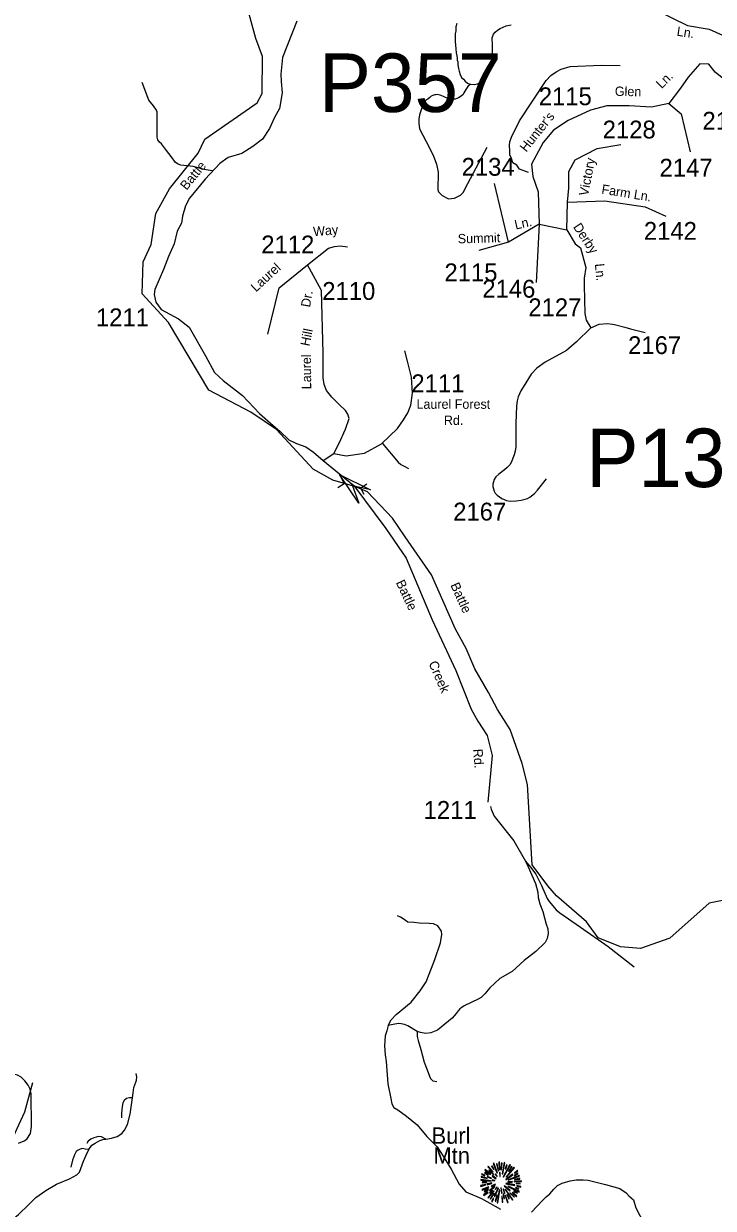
# Model space of a CAD drawing. Extents: x 884530 to 1028605, y 526725 to 653634.
# Drawn here: x 938802 to 943636, y 588671 to 596972 of the extents above; entities that cross this region are included whole.
import ezdxf

# ---------------------------------------------------------------- set-up
doc = ezdxf.new("R2010")
doc.units = 0
for name, color, linetype in [('Exist Geographical Mountain Summit CELL', 7, 'Continuous'), ('Exist Geographical Mountain Summit Label', 7, 'Continuous'), ('Exist Hydrographic Creek Single Shore', 7, 'Continuous'), ('Exist Hydrographic Creek Single Shore Label', 7, 'Continuous'), ('Exist Road Non-System Type 51', 7, 'Continuous'), ('Exist Road Secondary Structure Pipe Attributed CELL', 7, 'Continuous'), ('Exist Road Secondary Structure Pipe CELL', 7, 'Continuous'), ('Exist Road Secondary Structure Pipe Number Label', 7, 'Continuous'), ('Exist Road Secondary Type 51 Attributed', 7, 'Continuous'), ('Exist Road Secondary Type 51 Label', 7, 'Continuous'), ('Exist Road Secondary Type 51 Number Label', 7, 'Continuous')]:
    doc.layers.add(name, color=color, linetype=linetype)

msp = doc.modelspace()

# ---------------------------------------------------------------- linework, layer by layer
at = {"layer": 'Exist Geographical Mountain Summit CELL'}
for points in [[(942034.4, 588937.6), (942074.1, 588907), (942076.3, 588909.2), (942038.1, 588942)], [(942054.8, 588962.3), (942090.8, 588924.9), (942094.1, 588927.4), (942058.8, 588967)], [(942062.8, 588934.6), (942095.5, 588905.6), (942097.7, 588907.8), (942065.7, 588939.8)], [(942082.4, 588963.7), (942098, 588942), (942099.8, 588943.4), (942086.4, 588967.8)], [(942093.3, 588985.6), (942119.5, 588918.7), (942122.4, 588919.7), (942098.4, 588988.1)], [(942127.1, 588933.6), (942129.6, 588934.3), (942120.6, 588982.2), (942116.2, 588981.2)], [(942131.8, 588995), (942135.9, 588943), (942139.1, 588943.4), (942137.7, 588996.1)], [(942147.9, 588940.9), (942151.8, 588940.9), (942155.4, 588988.1), (942150, 588988.1)], [(942159.8, 588912.5), (942174.7, 588989.5), (942169.2, 588991.3), (942156.6, 588913.2)], [(942163.1, 588890.7), (942166, 588888.9), (942214.7, 588973.5), (942209.2, 588977.2)], [(942177.6, 588947.7), (942180.9, 588946.6), (942190.4, 588973.5), (942185.6, 588975.3)], [(942184.1, 588892.1), (942186.4, 588890), (942241.9, 588954.3), (942237.9, 588959)], [(942221.6, 588963.7), (942200.5, 588930.3), (942203.5, 588929.2), (942225.9, 588960.5)], [(942241.9, 588920.1), (942243.8, 588917.6), (942266.6, 588933.9), (942263, 588937.6)], [(942006, 588867.4), (942078.1, 588860.5), (942078.4, 588863.4), (942006, 588872.5)], [(942008.7, 588888.5), (942050.1, 588879), (942051.2, 588882.3), (942009.8, 588893.2)], [(942011.6, 588907.8), (942034, 588899.1), (942035.2, 588902), (942013, 588912.9)], [(942018.1, 588850), (942047.9, 588851.4), (942047.9, 588855.1), (942017, 588855.1)], [(942033.4, 588918.7), (942059.2, 588902.3), (942061.4, 588904.9), (942036.2, 588922.7)], [(942050.1, 588890.7), (942080.6, 588878.7), (942081.7, 588880.8), (942052.3, 588894.7)], [(942050.5, 588841), (942051.5, 588836.2), (942084.6, 588844.6), (942083.9, 588848.2)], [(942078.1, 588826.7), (942080.3, 588822), (942109, 588837.2), (942107.9, 588840.6)], [(942086.4, 588896.1), (942111.5, 588877.2), (942113.6, 588880.1), (942089, 588899.4)], [(942086.7, 588866.3), (942103.8, 588864.1), (942104.2, 588866.3), (942087.5, 588870.7)], [(942106.1, 588909.2), (942119.9, 588892.8), (942122, 588895), (942109.3, 588912.2)], [(942137.3, 588921.6), (942138.7, 588892.5), (942141.3, 588892.8), (942141.3, 588921.9)], [(942180.9, 588872.2), (942182.7, 588869.6), (942231.4, 588905.6), (942228.2, 588910)], [(942182.3, 588842.8), (942243.1, 588830.8), (942244.1, 588835.1), (942183.4, 588846.4)], [(942196.9, 588856.6), (942196.9, 588853.7), (942227, 588853.7), (942227.8, 588858.7)], [(942197.9, 588869.3), (942199, 588867), (942277.2, 588895.7), (942275.4, 588900.5)], [(942240.1, 588855.5), (942292.5, 588858.7), (942292.8, 588863.4), (942240.5, 588858.7)], [(942241.9, 588897.3), (942269.5, 588912.2), (942266.6, 588917.2), (942240.5, 588899.8)], [(942243.8, 588869.3), (942280.5, 588875.8), (942279, 588881.2), (942242.3, 588871.5)], [(942255, 588843.5), (942281.5, 588841.2), (942281.5, 588845.6), (942255.4, 588846.7)], [(942004.6, 588829.7), (942006, 588824.5), (942042.1, 588835.1), (942039.9, 588838.4)], [(942014.4, 588802), (942017, 588797.3), (942062.4, 588817.3), (942061, 588822)], [(942025.7, 588765.3), (942028.6, 588761.3), (942057, 588782.4), (942054.4, 588785.6)], [(942031.9, 588786), (942061, 588802.7), (942058.8, 588806.4), (942029.7, 588791.1)], [(942056.6, 588745.7), (942059.5, 588743.2), (942100.2, 588790.8), (942097.3, 588792.9)], [(942071.9, 588777), (942091.2, 588795.1), (942087.8, 588797.3), (942067.5, 588780.2)], [(942068.2, 588795.5), (942071.1, 588791.8), (942105.7, 588820.2), (942103.8, 588822.7)], [(942096.6, 588777), (942071.5, 588737.7), (942074.7, 588735.2), (942100.6, 588774.8)], [(942099.8, 588755.5), (942104.2, 588753.7), (942130.8, 588812.2), (942128.2, 588813)], [(942106.8, 588804.9), (942110, 588802), (942120.2, 588818.4), (942118.3, 588819.8)], [(942111.5, 588720.3), (942123.5, 588763.1), (942119.9, 588763.5), (942107.1, 588721.3)], [(942121.3, 588710.1), (942126, 588709), (942138.7, 588798.3), (942135.5, 588799.1)], [(942146.7, 588814), (942150.7, 588777), (942155.1, 588777.3), (942150, 588814.8)], [(942162.8, 588805.3), (942171.5, 588775.5), (942175.5, 588777.3), (942164.9, 588806.4)], [(942172.5, 588738.8), (942167.1, 588768.6), (942163.8, 588768.6), (942168.2, 588737.7)], [(942171.1, 588825.7), (942209.6, 588790.4), (942212.1, 588794.7), (942172.9, 588827.9)], [(942177.3, 588803.1), (942227.8, 588728.3), (942231.4, 588731.1), (942179.8, 588804.2)], [(942177.3, 588760.3), (942194.7, 588710.4), (942199, 588712.2), (942180.2, 588761)], [(942187.8, 588766), (942203.8, 588736.6), (942207.8, 588738.8), (942191.5, 588767.5)], [(942196.1, 588823.1), (942274.3, 588784.9), (942276.1, 588790.4), (942197.6, 588826)], [(942209.6, 588777.3), (942239.7, 588748.2), (942243.1, 588750.8), (942211.8, 588779.8)], [(942226.3, 588778), (942256.8, 588752.2), (942260.1, 588755.9), (942228.2, 588780.6)], [(942235.4, 588789), (942260.5, 588775.9), (942263, 588779.5), (942237.6, 588792.9)], [(942249.6, 588813), (942270.7, 588804.9), (942272.5, 588809.3), (942251, 588816.2)], [(942259.1, 588826.3), (942287.4, 588819.1), (942288.1, 588824.5), (942260.1, 588830.8)], [(942081.7, 588718.4), (942086.4, 588715.6), (942097.3, 588740.2), (942094.1, 588742.4)], [(942152.9, 588755.5), (942156.6, 588713), (942160.6, 588714), (942157.2, 588755.5)]]:
    msp.add_lwpolyline(points, close=True, dxfattribs=at)
at = {"layer": 'Exist Hydrographic Creek Single Shore'}
for points in [[(943782.9, 590844.9), (943606.5, 590809), (943332.5, 590564.2), (943125.1, 590492.5), (942986.9, 590502.4), (942829, 590566.6), (942748.5, 590679.3), (942536.2, 590859.6), (942477, 590931.2), (942365.9, 591076.9), (942333.9, 591640.6), (942296.8, 591788.8), (942212.9, 592025.9), (942124.1, 592166.7), (942060.6, 592286.2), (941964.4, 592452.2), (941902.9, 592594.6), (941828.6, 592728.3), (941660.8, 593109.5), (941475, 593376.6), (941386.8, 593507.7), (941211.6, 593692.4), (941122.7, 593728.8), (940969.3, 593772.8), (940830.4, 593851.1), (940573.5, 594128.6), (940394.4, 594250.3), (940099.6, 594403.9), (939816.5, 594878.9), (939631.9, 595079.5), (939639.8, 595302.5), (939694.4, 595426.1), (939727, 595642), (939825.1, 595814), (940025.8, 596065.9), (940071, 596163.5), (940438.8, 596418.6), (940474.4, 596483.5), (940475.5, 596742.7), (940429.8, 596868.3), (940324.6, 597254.9)], [(936105.3, 585081.1), (936369.8, 585037.6), (936778.8, 585049.1), (936839.7, 585123.3), (936938.6, 585551.3), (936941.3, 586092.7), (936919.1, 586168.6), (936927.8, 586411.3), (936868.3, 586612.7), (936773.8, 586768.8), (936767.5, 586824.7), (936727.6, 586878), (936712.8, 587160.5), (936783, 587257.6), (937200.6, 587511.7), (937468.6, 587775.4), (938034.1, 588430.2), (938569.9, 588954.3), (938700.6, 589109.3), (938809.1, 589346.7), (938866.6, 589552.2)]]:
    msp.add_lwpolyline(points, dxfattribs=at)
at = {"layer": 'Exist Road Non-System Type 51'}
for points in [[(941839, 596973.4), (941832.3, 596951.4), (941830.2, 596921.4), (941826.5, 596902.3), (941827.2, 596878.2), (941826.5, 596847.4), (941827.9, 596821.1), (941832.3, 596796.1), (941834.5, 596769.1), (941837.4, 596746.3), (941840.4, 596730.3), (941840.4, 596717.8), (941844.7, 596704.6), (941845.5, 596683.4), (941849.8, 596657.7), (941855, 596639.4), (941861.6, 596616.7), (941870.3, 596596.2), (941885.1, 596584.5), (941897.5, 596569.8), (941913.6, 596555.9), (941925.3, 596550.8), (941934.1, 596548.8)], [(941934.1, 596548.8), (941962.1, 596545.6), (941983.2, 596550.1), (942006.6, 596558.1), (942023.3, 596569.6), (942039.9, 596589.5), (942049.8, 596609.4), (942069.5, 596635.7), (942083.6, 596662.1), (942090.6, 596722), (942088.8, 596774.8), (942088.8, 596822.3), (942087.1, 596873.4), (942095.3, 596899.2), (942107, 596912.9), (942123.1, 596926.1), (942141, 596937.9), (942162.3, 596949), (942184.3, 596957.2), (942218.2, 596963.9)], [(942340.3, 595928.4), (942278.1, 595953.7), (942258.9, 595980.5), (942232, 595997.8), (942220.5, 596028.4), (942210.9, 596053.4), (942209, 596082.2), (942207, 596118.6), (942210.9, 596145.5), (942220.5, 596176.1), (942278.1, 596292.2), (942464.9, 596573.9), (942497.5, 596608.7), (942535, 596635.6), (942570.8, 596654.2), (942633.1, 596672.9), (942851.1, 596680.8), (942983, 596679.6)], [(940122.1, 595940.5), (940067.3, 595950.3), (939991, 595972), (939903.6, 595981.5), (939884.1, 595987.6), (939867.1, 595998.5), (939835.5, 596041), (939803.9, 596084.8), (939768.7, 596131), (939752.9, 596141.9), (939741.9, 596157.7), (939737.1, 596178.3), (939737.3, 596352.8), (939733.5, 596365.3), (939710.8, 596396.7), (939679.5, 596436.9), (939633, 596560)], [(941934.1, 596548.8), (941914.8, 596531.6), (941909.9, 596524.3), (941902.1, 596512.3), (941894.9, 596498.9), (941888.3, 596487.9), (941882.3, 596475.4), (941867.6, 596463.3), (941849.9, 596452.9), (941837.8, 596447.2), (941826.2, 596443.6), (941814.5, 596442.3), (941802.9, 596443.4), (941791.1, 596445.8), (941781.8, 596447.7), (941771.1, 596450.5), (941757.9, 596455.4), (941744, 596461.7), (941732.1, 596467.9), (941721.5, 596471.8), (941710.8, 596473.2), (941699.6, 596475.7), (941690.8, 596474.7), (941680.7, 596473.2), (941657.3, 596463.5), (941648, 596456.2), (941633.9, 596444.5), (941622.1, 596435.3), (941611, 596419.2), (941594.9, 596389.7), (941577.4, 596334.2), (941572.7, 596302.4), (941571.1, 596275.4), (941577.4, 596235.8), (941623.5, 596146.9), (941672.6, 596050.1), (941696.5, 595988.2), (941707.5, 595932.7), (941706, 595810.6), (941710.7, 595793.1), (941736.1, 595767.7), (941778.9, 595745.5), (941821.9, 595750.3), (941863.1, 595770.9), (941883.7, 595790), (941915.5, 595853.4), (942050.3, 596107.3)], [(941316.7, 594031.3), (941426.3, 593898.4), (941445.4, 593883.7), (941470.3, 593870.5), (941499.7, 593855.8)], [(942074.4, 591485.7), (942079, 591467.8), (942101, 591419.1), (942238.6, 591245.8), (942320.7, 591103.5)], [(942320.7, 591103.5), (942337.4, 591062.9), (942389.6, 590946.3), (942405.9, 590885.5), (942407.5, 590849.7), (942419.4, 590804.9), (942440.3, 590750.8), (942464, 590661.1), (942475.7, 590629.6), (942479.1, 590595.7), (942470.9, 590560.6), (942456.6, 590533.4), (942393, 590471.2), (942310.8, 590407.4), (942225.6, 590331.3), (942140.6, 590281.3), (942070.8, 590214.6), (942033.9, 590173), (942007.9, 590149.1), (941987.5, 590135.5), (941943.3, 590114.4), (941890.2, 590088.9), (941873.3, 590077.8), (941860.1, 590068.9), (941848.1, 590054.1), (941832.9, 590034.9), (941805.3, 590002.2), (941702.2, 589918.7), (941656.8, 589900.5), (941620.3, 589896), (941583.9, 589902.1), (941559.6, 589909.7)], [(942320.7, 591103.5), (942353.7, 591061.2), (942391.1, 591012.7), (942433.1, 590931.7), (942472.1, 590842.1), (942484.6, 590820.7), (942534.4, 590762.1), (942560.8, 590740.4), (942704.4, 590640.8), (942899.8, 590506.5), (943081.9, 590363.3)], [(941357, 589951.5), (941377.9, 589991.7), (941413.7, 590029), (941517.4, 590115), (941581.7, 590194.1), (941624.3, 590256.6), (941659.9, 590352.8), (941685.3, 590414), (941724, 590531.9), (941733, 590588.5), (941730, 590612.4), (941706.1, 590649.8), (941674.8, 590664.7), (941644.9, 590666.1), (941577.6, 590667.8), (941537.2, 590672.8), (941495.7, 590676.6), (941461.5, 590699), (941443.8, 590710.8), (941421.3, 590720.1)], [(941357, 589951.5), (941346.5, 589914.1), (941336.1, 589878.3), (941331.7, 589809.7), (941336.1, 589747), (941342.6, 589700.4), (941354.5, 589542.4), (941375.7, 589440), (941382.3, 589403.8), (941395.9, 589377), (941425.6, 589360.5), (941485.4, 589315.8), (941561.4, 589256.1), (941627.7, 589173.5), (941699.8, 589101.1), (941743.5, 589037.2), (941798.2, 588943.9), (941835.9, 588875.6), (941855.2, 588839.8), (941901.6, 588786.1), (942010.6, 588738.4), (942144.9, 588665.1)], [(941559.6, 589909.7), (941495.9, 589949.1), (941471.7, 589958.2), (941448.4, 589963.2), (941432.8, 589965), (941403.2, 589961.9), (941379.9, 589957.4), (941357, 589951.5)], [(941559.6, 589909.7), (941559.6, 589874.8), (941566.9, 589845.7), (941587, 589784.4), (941608.6, 589694.9), (941631.1, 589640.4), (941646.7, 589597.5), (941654.7, 589581.1), (941671.1, 589563.8), (941698.8, 589559.8)], [(938764.5, 589127), (938805.4, 589142.9), (938823.9, 589156.1), (938850.3, 589194.3), (938856.9, 589243.2), (938856.9, 589313.1), (938854.7, 589403), (938854.7, 589472.6), (938847.4, 589506.4), (938832.6, 589533.8), (938810.5, 589564.4), (938784.1, 589589.7), (938758.8, 589603.4), (938730.3, 589609.7), (938700.8, 589607.6), (938664.9, 589603.4), (938628, 589597.1), (938601.6, 589592.8)], [(939564.3, 589443.8), (939568.3, 589479.4), (939574.9, 589517.7), (939588.2, 589554.7), (939592.1, 589569.2), (939594.8, 589591.6), (939590.8, 589615.4)], [(939377, 589156.1), (939416.6, 589162.6), (939457.5, 589173.2), (939489.2, 589195.6), (939507.6, 589218.1), (939530.1, 589259), (939548.5, 589330.2), (939564.3, 589443.8)], [(939564.3, 589443.8), (939544.6, 589445.1), (939522.2, 589441.1), (939506.3, 589426.6), (939497.1, 589409.5), (939491.8, 589384.4), (939490.5, 589360.6), (939487.8, 589335.6), (939486.5, 589305.2)], [(939377, 589156.1), (939346.5, 589172), (939325.5, 589174.5), (939292.5, 589165.3), (939271.4, 589154.8), (939254.2, 589141.5), (939244.3, 589124.3)], [(939258.2, 589082.1), (939280.6, 589112.5), (939301.8, 589128.3), (939334.8, 589145.5), (939357.2, 589152.1), (939377, 589156.1)], [(938592.9, 588494.8), (938645.7, 588531.8), (938676, 588555.5), (938765.9, 588628), (938837.1, 588698.1), (938887.3, 588745.5), (938955.9, 588795.7), (939032.5, 588839.3), (939122.2, 588877.5), (939175, 588905.2), (939192.2, 588923.7), (939221.3, 589001.6), (939239.7, 589042.6), (939258.2, 589082.1)], [(939258.2, 589082.1), (939231.7, 589084.7), (939212, 589088.7), (939197.4, 589084.7), (939184.3, 589078.2), (939168.5, 589069), (939157.9, 589046.5), (939143.4, 589008.2), (939131.5, 588959.4)], [(942362.7, 588642.9), (942400, 588683.2), (942441.7, 588728), (942465.6, 588751.8), (942489.5, 588771.2), (942519.3, 588805.5), (942544.7, 588830.9), (942577.5, 588847.3), (942632.7, 588863.8), (942676, 588871.2), (942723.8, 588869.7), (942759.6, 588868.2), (942880.4, 588836.9), (942923.7, 588826.4), (942980.4, 588808.5), (943025.9, 588778.5), (943045, 588758.6), (943077.4, 588729.4), (943092.4, 588674.2), (943180.3, 588507.1)]]:
    msp.add_lwpolyline(points, dxfattribs=at)
at = {"layer": 'Exist Road Secondary Structure Pipe Attributed CELL'}
msp.add_lwpolyline([(941150.9, 593611.6), (941014.7, 593813.8), (941233.8, 593706.8), (941106.7, 593733.7)], close=True, dxfattribs=at)
at = {"layer": 'Exist Road Secondary Structure Pipe CELL'}
for p, q in [((941005, 593722.8), (941048.2, 593749.4)), ((941024.1, 593794), (941048.2, 593749.4)), ((941165.1, 593718.1), (941048.2, 593749.4)), ((941208.3, 593744.7), (941165.1, 593718.1)), ((941189.2, 593673.4), (941165.1, 593718.1))]:
    msp.add_line(p, q, dxfattribs=at)
at = {"layer": 'Exist Road Secondary Type 51 Attributed'}
for points in [[(942429.1, 597565.7), (942505.5, 597486.2), (942661.4, 597339.1), (942787.9, 597177.2), (943011.4, 597109.5), (943240.8, 597065.4), (943454.6, 596960.4), (943607.5, 596933.9), (943701.6, 596892.7), (943775.2, 596775), (943748.4, 596552.6)], [(940717.6, 596989.2), (940616.6, 596735.3), (940603.9, 596617.8), (940605.9, 596566.2), (940613.8, 596487), (940594, 596378.9), (940559.6, 596315.1), (940524.6, 596238.3), (940476.5, 596163.2), (940407.7, 596111.3), (940330.7, 596063.7), (940235.6, 596034.1), (940175.7, 595992), (940073.4, 595882.5), (939964.4, 595749.5), (939935.4, 595694.9), (939914.6, 595623.1), (939908.7, 595573.4), (939878.7, 595517.5), (939855.7, 595428.7), (939818, 595341.4), (939782.4, 595250.3), (939721, 595109.5), (939717, 595073.8), (939728.9, 595020.3), (939766.6, 594969.8), (939887.7, 594903.6), (939963, 594845.1), (940075.8, 594644.3), (940139.9, 594527.3), (940201.1, 594471.5), (940334.9, 594365.6), (940454.6, 594240.1), (940532.6, 594173.2), (940599.5, 594114.7), (940660.8, 594056.1), (940713.7, 594031), (940780.6, 594005.9), (940833.5, 593969.7), (940900.4, 593911.2)], [(943748.4, 596552.6), (943649.3, 596633.7), (943604.3, 596687.7), (943541.3, 596692.2), (943460.3, 596597.6), (943406.3, 596521.1), (943325.3, 596413.1)], [(943325.3, 596413.1), (943204, 596387.9), (943046.6, 596396.9), (942889.1, 596396.9), (942776.6, 596365.3), (942619.1, 596293.3), (942515.7, 596225.8), (942443.7, 596140.2), (942362.7, 595987.2), (942371.7, 595901.6), (942407.7, 595793.6), (942416.7, 595568.4)], [(943325.3, 596413.1), (943410.8, 596341), (943473.8, 596075.4)], [(942614.6, 595721.5), (942623.6, 595820.6), (942623.6, 595937.6), (942668.6, 596018.7), (942822.2, 596097.7), (942988.1, 596126.7)], [(942200.7, 595442.4), (942101.7, 595852.1)], [(942614.6, 595721.5), (942875.6, 595730.5), (943159, 595690), (943303, 595622.5)], [(942610.1, 595527.9), (942614.6, 595721.5)], [(942416.7, 595568.4), (942200.7, 595442.4)], [(942416.7, 595568.4), (942394.2, 595158.7)], [(942416.7, 595568.4), (942610.1, 595527.9)], [(942610.1, 595527.9), (942668.6, 595428.9), (942705.9, 595401.2), (942742.6, 595262.9), (942729.9, 595189.5), (942729.9, 595138.6), (942735.5, 594942.4), (942745.4, 594894.4), (942777.9, 594840.8)], [(940791.8, 595282.7), (940937.7, 595398.3), (940981.8, 595411.9), (941019.6, 595415.1), (941071.8, 595408.2)], [(942200.7, 595442.4), (941993.7, 595383.8)], [(940513.7, 594796), (940593.4, 595122), (940791.8, 595282.7)], [(940976.7, 593959.2), (941013.9, 594032.8), (941058.5, 594131.9), (941083.3, 594206.3), (941075.2, 594236.7), (941058.4, 594261.9), (941015.4, 594300.7), (940961.9, 594355.3), (940925.1, 594401.5), (940909.4, 594444.6), (940901, 594489.8), (940902, 594664.1), (940890.1, 595103.3), (940791.8, 595282.7)], [(942777.9, 594840.8), (942676.2, 594741.9), (942608.1, 594682.6), (942458.4, 594600.8), (942399.4, 594558.4), (942359.8, 594516.1), (942303.3, 594425.7), (942287.8, 594400.3), (942268, 594356.5), (942262.3, 594328.3), (942256.2, 594294.2), (942252.4, 594170), (942251.5, 594054.4), (942251, 594007.9), (942247.7, 593977), (942239.7, 593950), (942220, 593896.3), (942210.1, 593880.8), (942191.4, 593862.5), (942172.5, 593845.3), (942131.8, 593816.6), (942110.9, 593796.1), (942099.8, 593778.7), (942095.4, 593762.2), (942090.4, 593745.8), (942091.1, 593729.8), (942099.6, 593697.3), (942108, 593682.5), (942120.8, 593667.6), (942154.7, 593645.1), (942187.6, 593630.6), (942211.7, 593626.1), (942255, 593627.8), (942288.9, 593632.3), (942318.5, 593639.4), (942333.4, 593644.9), (942349.6, 593654.9), (942382.7, 593680.1), (942404.7, 593702.9), (942466.9, 593782)], [(942777.9, 594840.8), (942835.8, 594866.2), (942893.7, 594870.4), (942929.1, 594866.2), (942944.6, 594863.4), (943016, 594846.5), (943056.2, 594835.1), (943159.3, 594808.3)], [(940976.7, 593959.2), (941061.6, 593943.6), (941192.2, 593963.4), (941310.7, 594028.1), (941421.7, 594134.8), (941464.7, 594195.7), (941494.1, 594245.1), (941515.1, 594299.7), (941527.7, 594382.6), (941520.4, 594496.1), (941493.1, 594608.5), (941474.2, 594679.9)], [(940900.4, 593911.2), (940976.7, 593959.2)], [(940900.4, 593911.2), (941116.6, 593735.2), (941341.1, 593433.7), (941482.9, 593226.7), (941666.1, 592795), (941831.6, 592440.2), (941938, 592168.2), (941985.2, 592085.4), (942050.2, 591984.8), (942085.7, 591842.9), (942056.2, 591517.7)]]:
    msp.add_lwpolyline(points, dxfattribs=at)

# ---------------------------------------------------------------- texts
at = {"layer": 'Exist Geographical Mountain Summit Label'}
for s, p in [('Burl', (941661, 589123)), ('Mtn', (941674.2, 588983))]:
    msp.add_text(s, height=114.83, dxfattribs=at).set_placement(p)
at = {"layer": 'Exist Hydrographic Creek Single Shore Label'}
msp.add_text('Battle', height=65.62, rotation=294.43094, dxfattribs=at).set_placement((941791.9, 593038.2))
msp.add_text('Battle', height=65.62, rotation=294.43094, dxfattribs=at).set_placement((941791.9, 593038.2))
at = {"layer": 'Exist Road Secondary Structure Pipe Number Label'}
for s, p in [('P357', (940870.7, 596353.6)), ('P132', (942746, 593724.9))]:
    msp.add_text(s, height=410.1, dxfattribs=at).set_placement(p)
at = {"layer": 'Exist Road Secondary Type 51 Label'}
for s, rotation, p in [('Ln.', 351.40374, (943377, 596888.7)), ('Ln.', 44.51395, (943273.3, 596512.8)), ('Glen', 358.90169, (942945.6, 596466.8)), ("Hunter's", 51.224, (942324.8, 596068.2)), ('Battle', 50.66721, (939943.3, 595801.4)), ('Victory', 79.08978, (942758, 595761.2)), ('Farm Ln.', 350.76811, (942849.4, 595782.2)), ('Ln.', 12.77121, (942251.1, 595529.2)), ('Derby', 303.46047, (942650.9, 595548)), ('Way', 4.53414, (940833.7, 595483)), ('Summit', 1.54963, (941845.9, 595432.5)), ('Laurel', 42.73521, (940430.3, 595088.4)), ('Ln.', 275.621, (942805.9, 595288.8)), ('Dr.', 80.22946, (940809, 594981.6)), ('Hill', 78.52792, (940805.1, 594708.7)), ('Laurel', 90.38864, (940817.4, 594410.9)), ('Battle', 295.26991, (941409.2, 593056)), ('Creek', 293.47111, (941638.8, 592490.1)), ('Rd.', 273.787, (941953.4, 591888.6))]:
    msp.add_text(s, height=65.62, rotation=rotation, dxfattribs=at).set_placement(p)
for s, height, p in [('Laurel Forest', 65.617, (941555.5, 594273.5)), ('Rd.', 65.62, (941747.4, 594160.4))]:
    msp.add_text(s, height=height, dxfattribs=at).set_placement(p)
at = {"layer": 'Exist Road Secondary Type 51 Number Label'}
for s, p in [('2115', (942412.9, 596401.1)), ('2126', (943560.2, 596229.5)), ('2128', (942860.8, 596168.3)), ('2134', (941872.1, 595906.8)), ('2147', (943259.2, 595900.4)), ('2142', (943149.4, 595457.9)), ('2112', (940467.3, 595362.4)), ('2115', (941751.5, 595167.4)), ('2110', (940895, 595036.8)), ('2146', (942017.1, 595052.4)), ('2127', (942339.6, 594922.4)), ('1211', (939308.3, 594852)), ('2167', (943039.1, 594657.1)), ('2111', (941519.7, 594389.7)), ('2167', (941812.9, 593490.7)), ('1211', (941605.8, 591399.8))]:
    msp.add_text(s, height=125, dxfattribs=at).set_placement(p)

doc.saveas('drawing.dxf')
